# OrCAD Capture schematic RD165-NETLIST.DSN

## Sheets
1 3: size A3
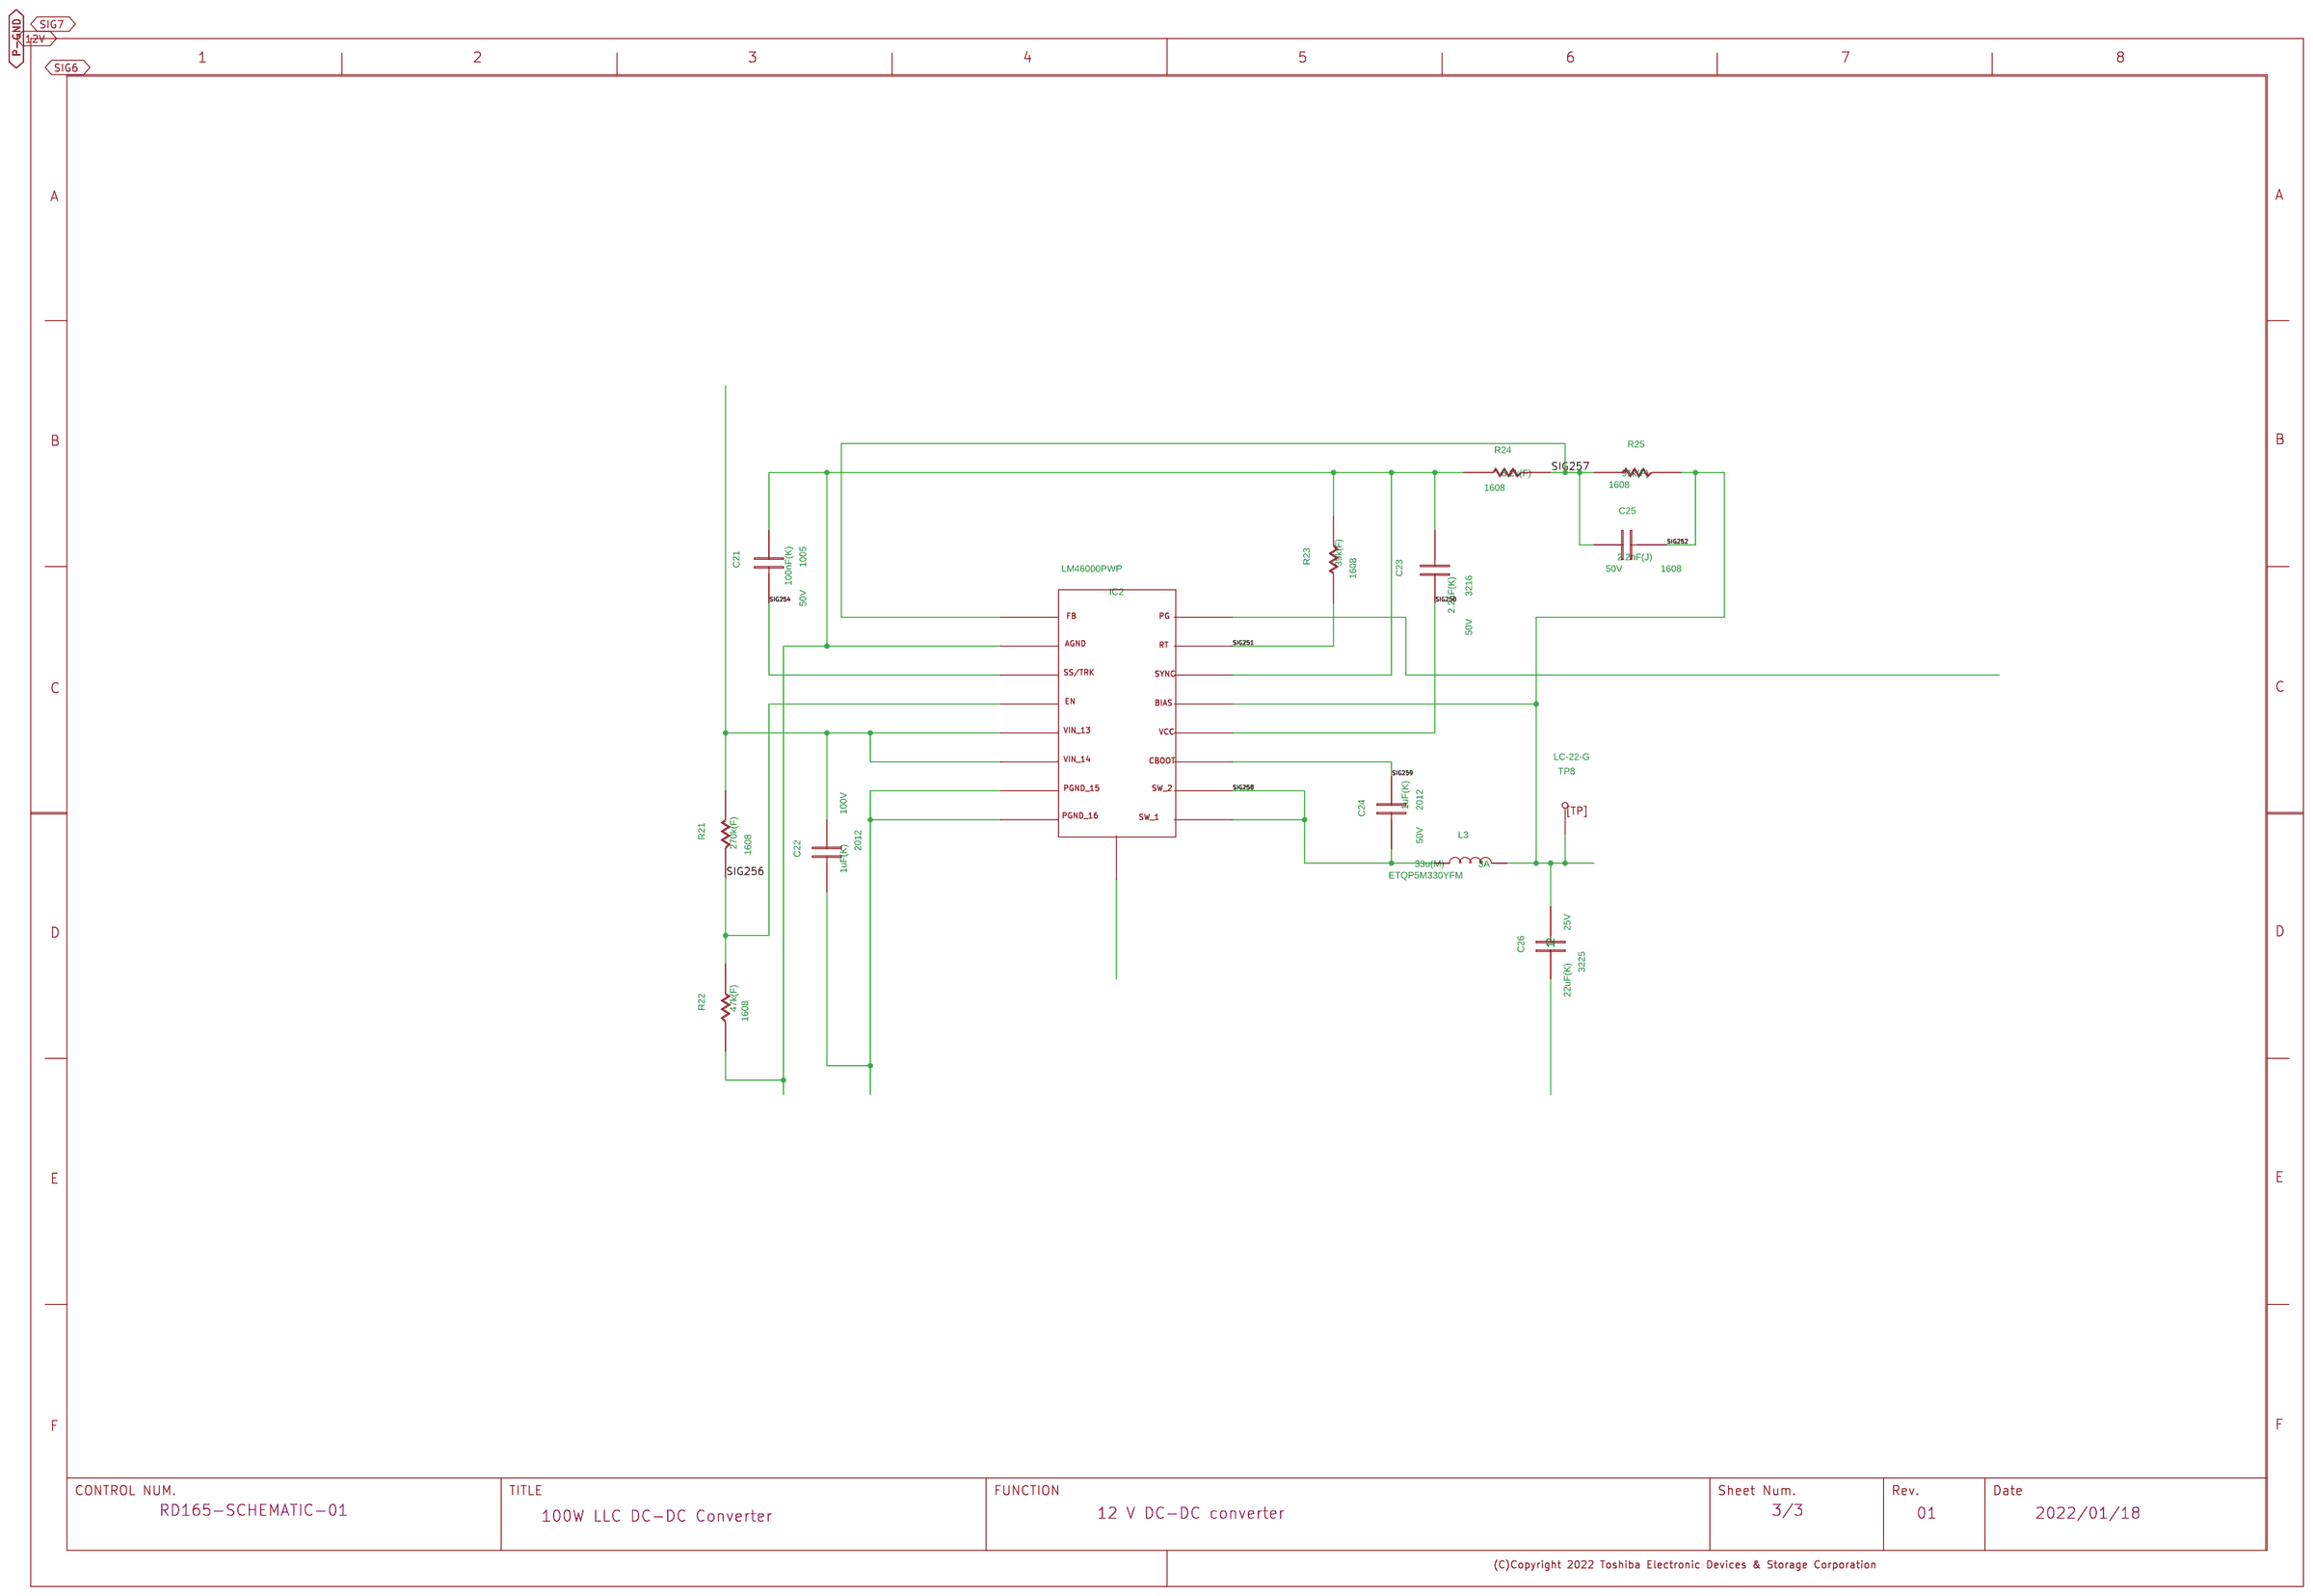
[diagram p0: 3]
2 2: size A3
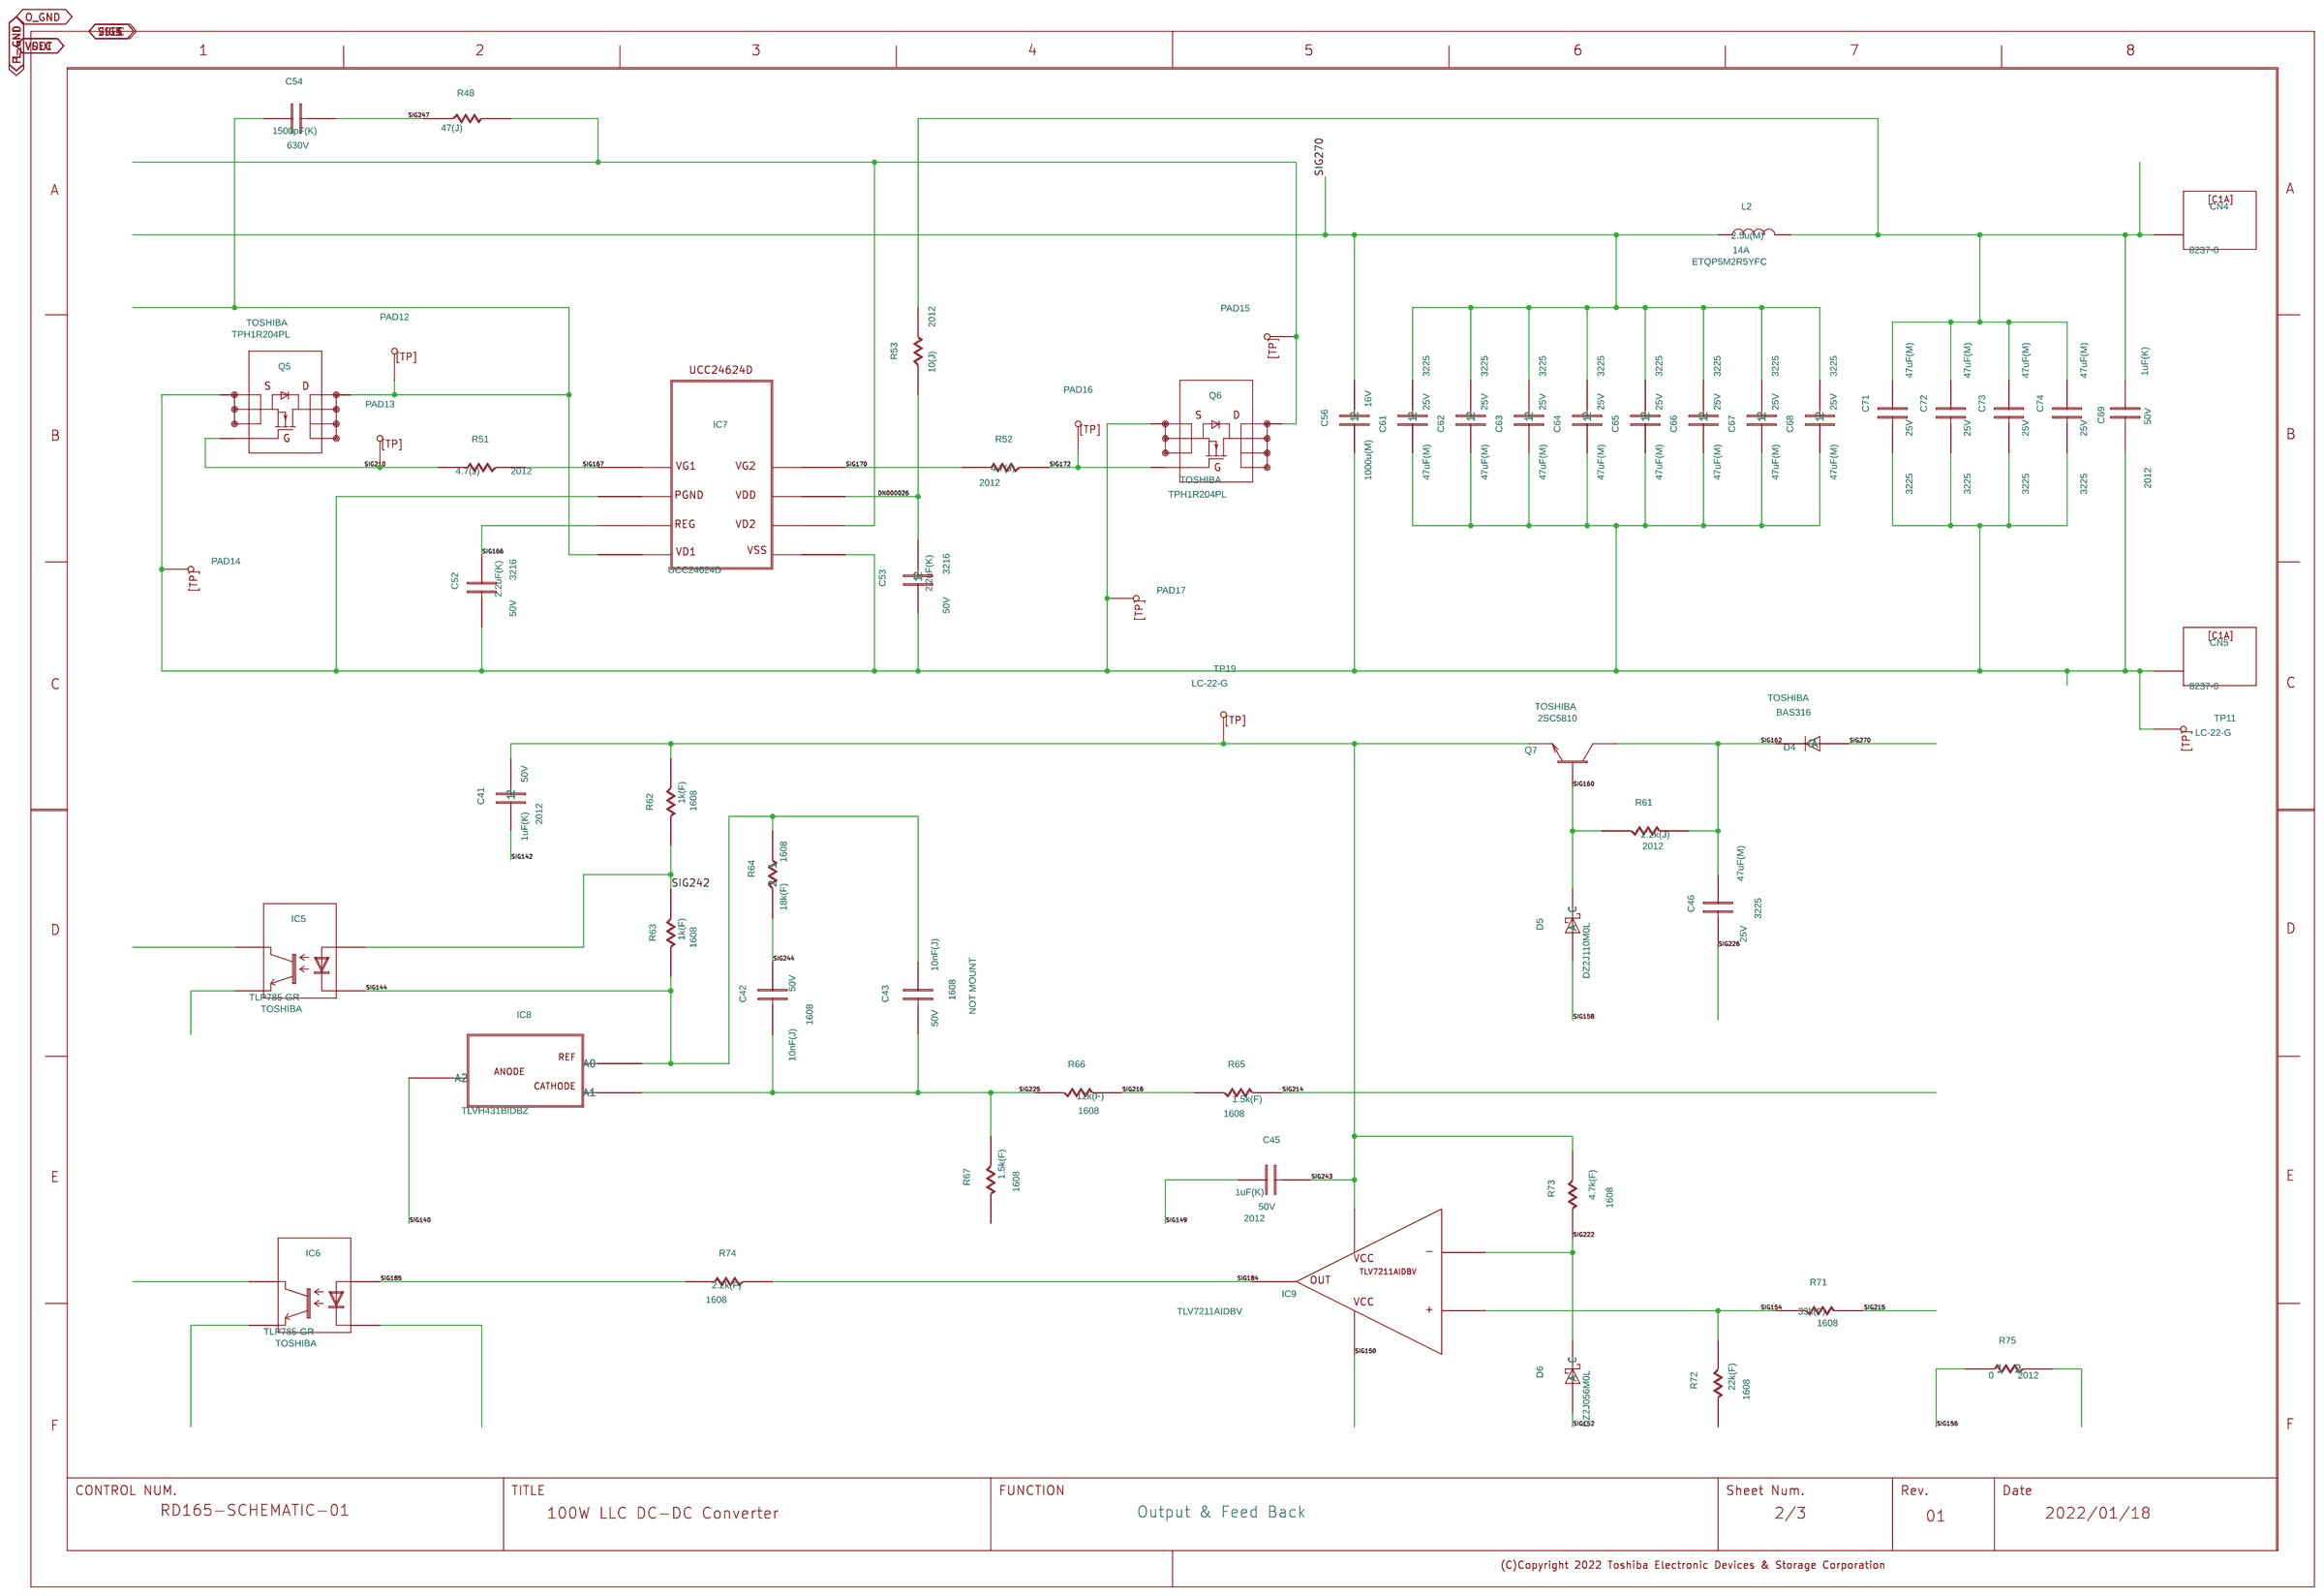
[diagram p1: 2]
3 1: size A3
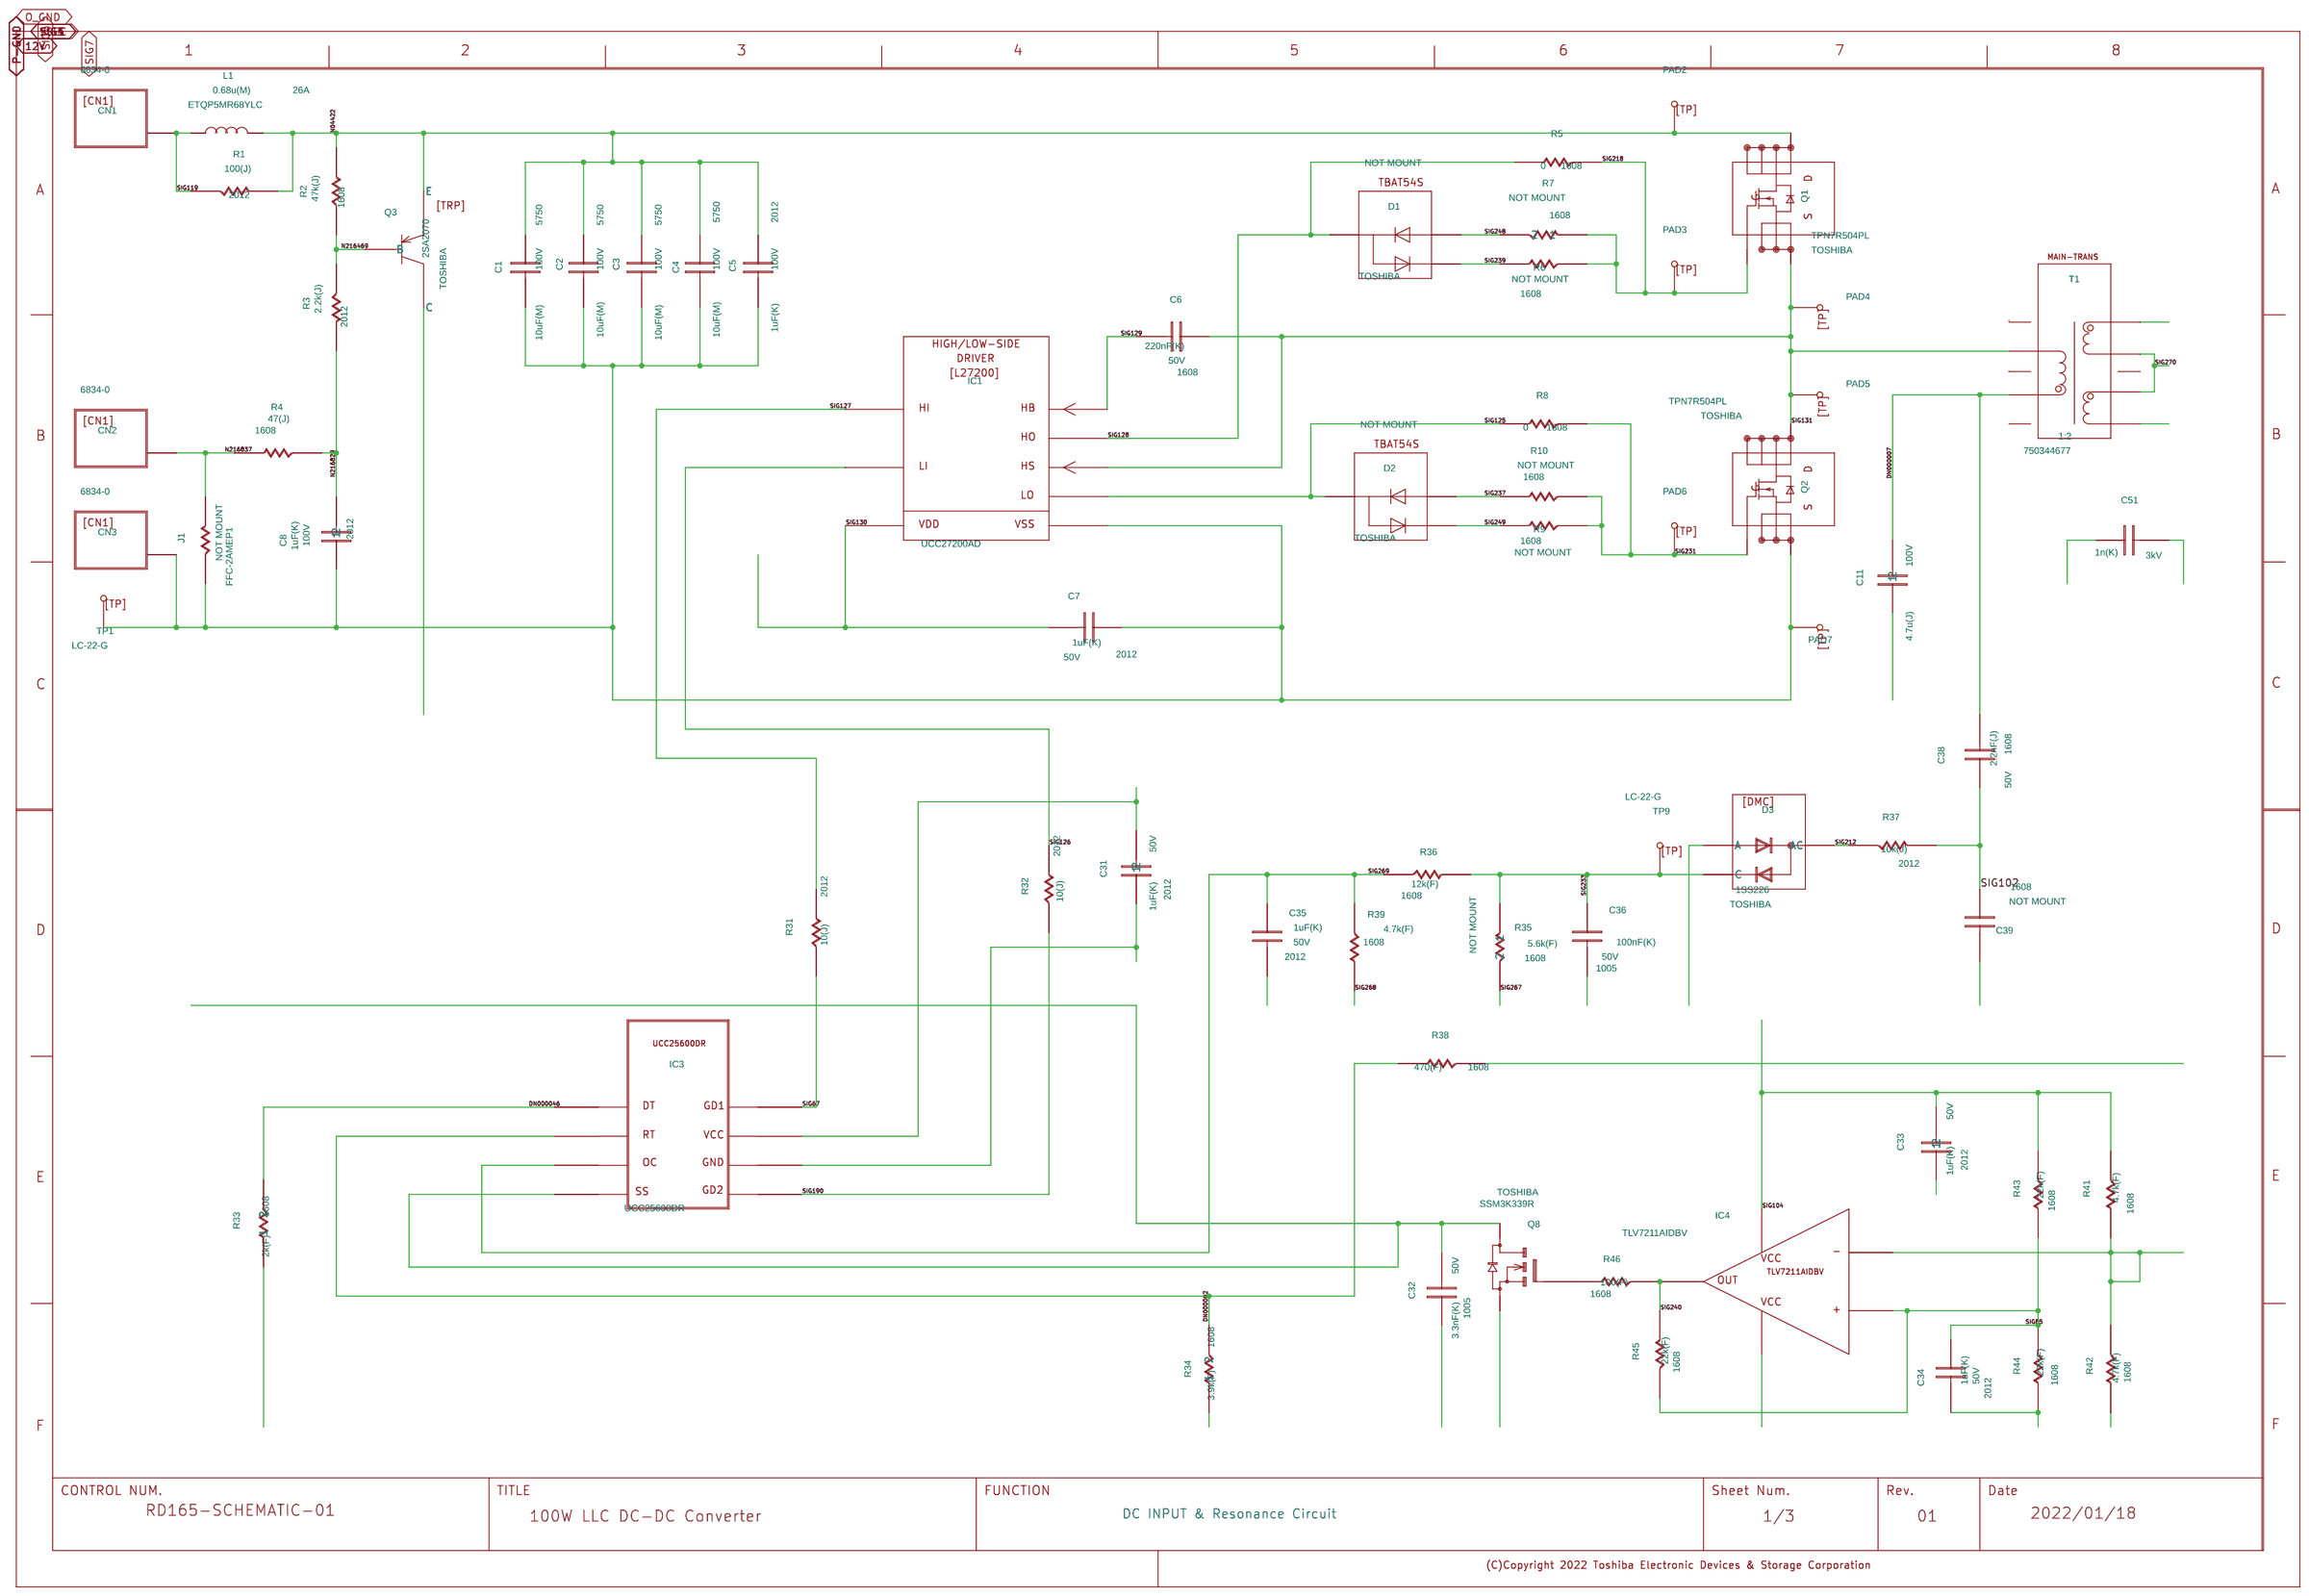
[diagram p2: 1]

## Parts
sheet 1
C1  C
C2  C
C3  C
C4  C
C5  C
C6  C
C7  C
C8  C
C11  C
C31  C
C32  C
C33  C
C34  C
C35  C
C36  C
C38  C
C39  C
C51  C
CN1  CN1
CN2  CN1
CN3  CN1
D1  TBAT54S
D2  TBAT54S
D3  DMC
IC1  L27200
IC3  UCC25600DR
IC4  TLV7211AIDBV
J1  R
L1  L
PAD2  TP
PAD3  TP
PAD4  TP
PAD5  TP
PAD6  TP
PAD7  TP
Q1  TPN7B504PL
Q2  TPN7B504PL
Q3  TRP
Q8  MFNF
R1  R
R2  R
R3  R
R4  R
R5  R
R6  R
R7  R
R8  R
R9  R
R10  R
R31  R
R32  R
R33  R
R34  R
R35  R
R36  R
R37  R
R38  R
R39  R
R41  R
R42  R
R43  R
R44  R
R45  R
R46  R
T1  TRANS
TP1  TP
TP9  TP
U?#2  WAKU_DEF100
sheet 2
C41  C
C42  C
C43  C
C45  C
C46  C
C52  C
C53  C
C54  C
C56  C
C61  C
C62  C
C63  C
C64  C
C65  C
C66  C
C67  C
C68  C
C69  C
C71  C
C72  C
C73  C
C74  C
CN4  C1A
CN5  C1A
D4  D
D5  SBD
D6  SBD
IC5  TLP785-GR
IC6  TLP785-GR
IC7  UCC24624D
IC8  HC086_GATE
IC9  TLV7211AIDBV
L2  L
PAD12  TP
PAD13  TP
PAD14  TP
PAD15  TP
PAD16  TP
PAD17  TP
Q5  TPH1R204PL
Q6  TPH1R204PL
Q7  2SC5810
R48  R
R51  R
R52  R
R53  R
R61  R
R62  R
R63  R
R64  R
R65  R
R66  R
R67  R
R71  R
R72  R
R73  R
R74  R
R75  R
TP11  TP
TP19  TP
U?#1  WAKU_DEF100
sheet 3
C21  C
C22  C
C23  C
C24  C
C25  C
C26  C
IC2  LM46000PWP
L3  L
R21  R
R22  R
R23  R
R24  R
R25  R
TP8  TP
U?#3  WAKU_DEF100

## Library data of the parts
C1-C4 = C: ADSMODELNAME: s_CX55Y5U106M50AT; CAPACITANCETOLE: M; CDBNAME: Chip5750_TD; CDMASTERCADCELG: DC848R; COMP: Chip5750_TD; COMPONENTTYPE: 4; FNLEADFREETHET1GT2GMCTH1: N_N_N; GCOUNT: 1; MAXGCOUNT: 1; NOMINALCAPACITA: 10u; OUMECLASSIFICATION: ƒZƒ‰ƒ~ƒbƒNƒRƒ“ƒfƒ“ƒT; OUMEMAKER: KYC ‹žƒZƒ‰; OUMEMAKERKATAMEI: CX55Y5U106M50AT; QUADMODEL: CON_10U; RATEDVOLTAGE: 50; SIZECODESMD: 5750; TEMPCHARACTERI2: E; VAL1: 10uF(M); VAL2: 100V
C5 = C: ADSMODELNAME: s_CGA4J3X7S2A105KT@@; CAPACITANCETOLE: K; CDBNAME: Chip2012_GS_1; CDMASTERCADCELG: KC0136; COMP: Chip2012_GS_1; COMPONENTTYPE: 4; FNLEADFREETHET1GT2GMCTH1: 3_2_N; GCOUNT: 1; MAXGCOUNT: 1; NOMINALCAPACITA: 1u; OUMECLASSIFICATION: ƒZƒ‰ƒ~ƒbƒNƒRƒ“ƒfƒ“ƒT; OUMEMAKER: TDK ‚s‚c‚j; OUMEMAKERKATAMEI: CGA4J3X7S2A105KT@@; PMPRODUCTSTYPEG: HEV; QUADMODEL: CON_1U; RATEDVOLTAGE: 100; SIZECODESMD: 2012; VAL1: 1uF(K); VAL2: 100V
C6 = C: ADSMODELNAME: s_CGA3E3X7R1H224KT@@; CAPACITANCETOLE: K; CDBNAME: Chip1608_GS_1; CDMASTERCADCELG: KCK0238; COMP: Chip1608_GS_1; COMPONENTTYPE: 4; FNLEADFREETHET1GT2GMCTH1: N_N_N; GCOUNT: 1; MAXGCOUNT: 1; NOMINALCAPACITA: 220n; OUMECLASSIFICATION: ƒZƒ‰ƒ~ƒbƒNƒRƒ“ƒfƒ“ƒT; OUMEMAKER: TDK ‚s‚c‚j; OUMEMAKERKATAMEI: CGA3E3X7R1H224KT@@; PMPRODUCTSTYPEG: DA; QUADMODEL: CON_220N; RATEDVOLTAGE: 50; SIZECODESMD: 1608; VAL1: 220nF(K); VAL2: 50V
C7 C24 C34 C45 C69 = C: ADSMODELNAME: s_CGA4J3X7R1H105KT@@; CAPACITANCETOLE: K; CDBNAME: Chip2012_GS_1; CDMASTERCADCELG: KC0159; COMP: Chip2012_GS_1; COMPONENTTYPE: 4; FNLEADFREETHET1GT2GMCTH1: 3_2_N; GCOUNT: 1; MAXGCOUNT: 1; NOMINALCAPACITA: 1u; OUMECLASSIFICATION: ƒZƒ‰ƒ~ƒbƒNƒRƒ“ƒfƒ“ƒT; OUMEMAKER: TDK ‚s‚c‚j; OUMEMAKERKATAMEI: CGA4J3X7R1H105KT@@; PMPRODUCTSTYPEG: DA; QUADMODEL: CON_1U; RATEDVOLTAGE: 50; SIZECODESMD: 2012; VAL1: 1uF(K); VAL2: 50V
C8 = C#1: ADSMODELNAME: s_CGA4J3X7R1H105KT@@; CAPACITANCETOLE: K; CDBNAME: Chip2012_GS_1; CDMASTERCADCELG: KC0159; COMP: Chip2012_GS_1; COMPONENTTYPE: 4; CaptureCellPackProp: C##1; FNLEADFREETHET1GT2GMCTH1: 3_2_N; GCOUNT: 1; MAXGCOUNT: 1; NOMINALCAPACITA: 1u; OUMECLASSIFICATION: ƒZƒ‰ƒ~ƒbƒNƒRƒ“ƒfƒ“ƒT; OUMEMAKER: TDK ‚s‚c‚j; OUMEMAKERKATAMEI: CGA4J3X7R1H105KT@@; PMPRODUCTSTYPEG: DA; QUADMODEL: CON_1U; RATEDVOLTAGE: 50; SIZECODESMD: 2012; VAL1: 1uF(K); VAL2: 100V
C11 = C#1: CDBNAME: CB182E0475***_AV; COMP: CB182E0475***_AV; COMPONENTTYPE: 4; CaptureCellPackProp: C##1; VAL1: 4.7u(J); VAL2: 100V
C31 C41 = C#1: ADSMODELNAME: s_CGA4J3X7R1H105KT@@; CAPACITANCETOLE: K; CDBNAME: Chip2012_GS_1; CDMASTERCADCELG: KC0159; COMP: Chip2012_GS_1; COMPONENTTYPE: 4; CaptureCellPackProp: C##1; FNLEADFREETHET1GT2GMCTH1: 3_2_N; GCOUNT: 1; MAXGCOUNT: 1; NOMINALCAPACITA: 1u; OUMECLASSIFICATION: ƒZƒ‰ƒ~ƒbƒNƒRƒ“ƒfƒ“ƒT; OUMEMAKER: TDK ‚s‚c‚j; OUMEMAKERKATAMEI: CGA4J3X7R1H105KT@@; PMPRODUCTSTYPEG: DA; QUADMODEL: CON_1U; RATEDVOLTAGE: 50; SIZECODESMD: 2012; VAL1: 1uF(K); VAL2: 50V
C32 = C: ADSMODELNAME: s_CGA2B3X7R1H103KT@@; CAPACITANCETOLE: K; CDBNAME: Chip1005_GS_2; CDMASTERCADCELG: KC0154; COMP: Chip1005_GS_2; COMPONENTTYPE: 4; FNLEADFREETHET1GT2GMCTH1: 3_0_N; GCOUNT: 1; MAXGCOUNT: 1; NOMINALCAPACITA: 10n; OUMECLASSIFICATION: ƒZƒ‰ƒ~ƒbƒNƒRƒ“ƒfƒ“ƒT; OUMEMAKER: TDK ‚s‚c‚j; OUMEMAKERKATAMEI: CGA2B3X7R1H103KT@@; PMPRODUCTSTYPEG: DA; QUADMODEL: CON_10N; RATEDVOLTAGE: 50; SIZECODESMD: 1005; VAL1: 3.3nF(K); VAL2: 50V
C33 = C#1: ADSMODELNAME: s_CGA4J3X7R1H105KTXXXS@@; CAPACITANCETOLE: K; CDBNAME: Chip2012_GS_1; CDMASTERCADCELG: KC0187; COMP: Chip2012_GS_1; COMPONENTTYPE: 4; CaptureCellPackProp: C##1; FNLEADFREETHET1GT2GMCTH1: 3_2_N; GCOUNT: 1; MAXGCOUNT: 1; NOMINALCAPACITA: 1u; OUMECLASSIFICATION: ƒZƒ‰ƒ~ƒbƒNƒRƒ“ƒfƒ“ƒT; OUMEMAKER: TDK ‚s‚c‚j; OUMEMAKERKATAMEI: CGA4J3X7R1H105KTXXXS@@; PMPRODUCTSTYPEG: DA; QUADMODEL: CON_1U; RATEDVOLTAGE: 50; SIZECODESMD: 2012; VAL1: 1uF(K); VAL2: 50V
C35 = C: CDBNAME: Chip2012_GS_1; COMP: Chip2012_GS_1; COMPONENTTYPE: 4; SIZECODESMD: 2012; VAL1: 1uF(K); VAL2: 50V
C36 = C: CDBNAME: Chip1005_GS_2; COMP: Chip1005_GS_2; COMPONENTTYPE: 4; SIZECODESMD: 1005; VAL1: 100nF(K); VAL2: 50V
C38 = C: ADSMODELNAME: s_GCM1885C1H222JA16D@@; CAPACITANCETOLE: J; CDBNAME: Chip1608_GS_1; CDMASTERCADCELG: KC0134; COMP: Chip1608_GS_1; COMPONENTTYPE: 4; FNLEADFREETHET1GT2GMCTH1: 3_2_N; GCOUNT: 1; MAXGCOUNT: 1; NOMINALCAPACITA: 2.2n; OUMECLASSIFICATION: ƒZƒ‰ƒ~ƒbƒNƒRƒ“ƒfƒ“ƒT; OUMEMAKER: MRT ºc»ì; OUMEMAKERKATAMEI: GCM1885C1H222JA16D@@; PMPRODUCTSTYPEG: HEV; QUADMODEL: CON_2.2N; RATEDVOLTAGE: 50; SIZECODESMD: 1608; VAL1: 2.2nF(J); VAL2: 50V
C39 C43 = C: ADSMODELNAME: s_CGA3E2C0G1H103JT@@; CAPACITANCETOLE: J; CDBNAME: Chip1608_GS_1; CDMASTERCADCELG: KC0134; COMP: Chip1608_GS_1; COMPONENTTYPE: 4; FNLEADFREETHET1GT2GMCTH1: 3_2_N; GCOUNT: 1; MAXGCOUNT: 1; NOMINALCAPACITA: 10n; NOTMOUNT: NOT MOUNT; OUMECLASSIFICATION: ƒZƒ‰ƒ~ƒbƒNƒRƒ“ƒfƒ“ƒT; OUMEMAKER: TDK ‚s‚c‚j; OUMEMAKERKATAMEI: CGA3E2C0G1H103JT@@; PMPRODUCTSTYPEG: HEV; QUADMODEL: CON_10N; RATEDVOLTAGE: 50; SIZECODESMD: 1608; VAL1: 10nF(J); VAL2: 50V
C51 = C: CDBNAME: Chip4632_AV; COMP: Chip4632_AV; COMPONENTTYPE: 4; VAL1: 1n(K); VAL2: 3kV
CN1-CN3 = CN1: CDBNAME: 6834-0-00-**-00-00-03-0_ML; CDMASTERCADCELG: CU0059; COMP: 6834-0-00-**-00-00-03-0_ML; COMPONENTTYPE: 4; FNLEADFREETHET1GT2GMCTH1: 9_1_N; GCOUNT: 1; MAXGCOUNT: 1; NUMBEROFCONTACT: 1; OUMECLASSIFICATION: ’P“ªƒvƒ‰ƒO; OUMEMAKER: SMK ƒGƒXƒGƒƒPƒC; OUMEMAKERKATAMEI: CMI1501-0101; OUMEPARTTYPE: CN; PLUGDIAMETER: 6m; RATEDVOLTAGE: 0; VAL1: 6834-0; VAL3: 6834-0
D1 D2 = TBAT54S: CDBNAME: TBAT54S_TS; COMP: TBAT54S_TS; COMPONENTTYPE: 4; NOTMOUNT: NOT MOUNT; USERCOMPTEXT3: TOSHIBA
D3 = DMC: ADSMODELNAME: s_1SS226_TE85R_; CDBNAME: 1SS226_TS; CDMASTERCADCELG: DD902A; COMP: 1SS226_TS; COMPONENTTYPE: 4; FNLEADFREETHET1GT2GMCTH1: 2_0_N; FORWARDVOLTAGEM: 0; GCOUNT: 1; MAXAVERAGEFORWA: 0; MAXGCOUNT: 1; MAXREPETITIVEPE: 0; MAXREVERSEVOLTA: 70; MOUNTINGFORMSMD: SMD; OUMECLASSIFICATION: ¬M_CI[h; OUMEMAKER: TSB “ŒŽÅ; OUMEMAKERKATAMEI: 1SS226(TE85R); OUMEPARTTYPE: D; PEAKFORWARDVOLT: 0; PMPRODUCTSTYPEG: PC1; REVERSECURRENT: 0; USERCOMPTEXT3: TOSHIBA; VAL1: 1SS226; VAL3: 1SS226; ZENERVOLTAGEMAX: 0; ZENERVOLTAGEMIN: 0
IC1 = L27200: CDBNAME: UCC272**AD_TI; CDMASTERCADCELG: I810D8; COMP: UCC272**AD_TI; COMPONENTTYPE: 4; FNLEADFREETHET1GT2GMCTH1: N_N_N; GCOUNT: 1; KIND: OTHER; MAXGCOUNT: 1; MOUNTINGFORMSMD: SMD; OUMECLASSIFICATION: ‚»‚Ì‘¼; OUMEMAKER: TII eLTXCXcc; OUMEMAKERKATAMEI: UCC27200D; OUMEPARTTYPE: IC; VAL1: UCC27200AD; VAL3: UCC27200AD
IC3 = UCC25600DR: CDBNAME: UCC25600D*_TI; COMP: UCC25600D*_TI; COMPONENTTYPE: 4
IC4 IC9 = TLV7211AIDBV: CDBNAME: TLV7211AIDBVR_TI; COMP: TLV7211AIDBVR_TI; COMPONENTTYPE: 4
J1 = R: CDBNAME: FFC-2AMEP1_HN; COMP: FFC-2AMEP1_HN; COMPONENTTYPE: 4; NOTMOUNT: NOT MOUNT; VAL1: FFC-2AMEP1; VAL3: FFC-2AMEP1
L1 = L: CDBNAME: ETQP5M***YLC_PN; COMP: ETQP5M***YLC_PN; COMPONENTTYPE: 4; VAL1: 0.68u(M); VAL2: 26A; VAL3: ETQP5MR68YLC
PAD2-PAD7 PAD12-PAD17 = TP: CDBNAME: TP_I_TH0.5_LC1.1_RC1.2_GS; COMP: TP_I_TH0.5_LC1.1_RC1.2_GS; COMPONENTTYPE: 4
Q1 Q2 = TPN7B504PL: CDBNAME: TPN7R504PL_TS_A; COMP: TPN7R504PL_TS_A; COMPONENTTYPE: 4; SAVEAREA0: -19342,-136,26697,27151; SAVECOUNT: 22; UPDATEDATE: 2019/09/20; UPDATETIME: 14:39:22; USERCOMPTEXT3: TOSHIBA; VAL1: TPN7R504PL; VAL3: TPN7R504PL
Q3 = TRP: ADSMODELNAME: s_2SA2070_TE12L_F_; CDBNAME: 2SA2070_TS; CDMASTERCADCELG: DQ901D; COMP: 2SA2070_TS; COMPONENTTYPE: 4; FNLEADFREETHET1GT2GMCTH1: N_N_N; GCOUNT: 1; MAXCBVOLTAGE: 0; MAXCEVOLTAGE: 0; MAXCOLLECTORCUR: -1; MAXDRAINCURRENT: 0; MAXDSVOLTAGE: 0; MAXEBVOLTAGE: 0; MAXGATECURRENT: 0; MAXGCOUNT: 1; MAXGDVOLTAGE: 0; MAXGSVOLTAGE: 0; MOUNTINGFORMSMD: SMD; OUMECLASSIFICATION: PNPoC|[gWX^; OUMEMAKER: TSB “ŒŽÅ; OUMEMAKERKATAMEI: 2SA2070(TE12L,F); OUMEPARTTYPE: Q; PMPRODUCTSTYPEG: HD1; USERCOMPTEXT3: TOSHIBA; VAL1: 2SA2070; VAL3: 2SA2070
Q8 = MFNF: CDBNAME: SSM3K339R_TS_A; COMP: SSM3K339R_TS_A; COMPONENTTYPE: 4; USERCOMPTEXT3: TOSHIBA; VAL1: SSM3K339R; VAL3: SSM3K339R
R1 = R: ADSMODELNAME: s_ERJP06J101V; CDBNAME: Chip2012_GS_1; CDMASTERCADCELG: KC0006; COMP: Chip2012_GS_1; COMPONENTTYPE: 4; FNLEADFREETHET1GT2GMCTH1: 2_2_N; GCOUNT: 1; MAXGCOUNT: 1; MOUNTINGFORMSMD: SMD; NOMINALRESISTAN: 100; OUMECLASSIFICATION: \ÊÀpÅèïRí; OUMEMAKER: NAE pi\jbNGNgjbNfoCX; OUMEMAKERKATAMEI: ERJP06J101V; PMPRODUCTSTYPEG: PC1-PCS; POWERRATING: 250m; QUADMODEL: RES_100; RESISTANCETOLER: J; SIZECODESMD: 2012; VAL1: 100(J); VAL2: 400mW
R2 = R: ADSMODELNAME: s_ERJ3GEYJ473V@@; CDBNAME: Chip1608_GS_1; CDMASTERCADCELG: KC0133; COMP: Chip1608_GS_1; COMPONENTTYPE: 4; FNLEADFREETHET1GT2GMCTH1: 3_2_N; GCOUNT: 1; MAXGCOUNT: 1; MOUNTINGFORMSMD: SMD; NOMINALRESISTAN: 47K; OUMECLASSIFICATION: \ÊÀpÅèïRí; OUMEMAKER: NAE pi\jbNGNgjbNfoCX; OUMEMAKERKATAMEI: ERJ3GEYJ473V@@; PMPRODUCTSTYPEG: HEV; POWERRATING: 100m; QUADMODEL: RES_47K; RESISTANCETOLER: J; SIZECODESMD: 1608; VAL1: 47k(J); VAL2: 100mW
R3 R61 = R: ADSMODELNAME: s_SG73P2ATTD222J@@; CDBNAME: Chip2012_GS_1; CDMASTERCADCELG: KC0135; COMP: Chip2012_GS_1; COMPONENTTYPE: 4; FNLEADFREETHET1GT2GMCTH1: 3_1_N; GCOUNT: 1; MAXGCOUNT: 1; MOUNTINGFORMSMD: SMD; NOMINALRESISTAN: 2.2K; OUMECLASSIFICATION: \ÊÀpÅèïRí; OUMEMAKER: KOA R[A; OUMEMAKERKATAMEI: SG73P2ATTD222J@@; PMPRODUCTSTYPEG: HEV; POWERRATING: 250m; QUADMODEL: RES_2.2K; RESISTANCETOLER: J; SIZECODESMD: 2012; VAL1: 2.2k(J); VAL2: 400mW
R4 = R: ADSMODELNAME: s_RK73B1JTTD470J@@; CDBNAME: Chip1608_GS_1; CDMASTERCADCELG: KC0133; COMP: Chip1608_GS_1; COMPONENTTYPE: 4; FNLEADFREETHET1GT2GMCTH1: 3_1_N; GCOUNT: 1; MAXGCOUNT: 1; MOUNTINGFORMSMD: SMD; NOMINALRESISTAN: 47; OUMECLASSIFICATION: \ÊÀpÅèïRí; OUMEMAKER: KOA R[A; OUMEMAKERKATAMEI: RK73B1JTTD470J@@; PMPRODUCTSTYPEG: HEV; POWERRATING: 100m; QUADMODEL: RES_47; RESISTANCETOLER: J; SIZECODESMD: 1608; VAL1: 47(J); VAL2: 100mW
R5 R8 = R: ADSMODELNAME: s_CR1_16_000V_HSF; CDBNAME: Chip1608_GS_1; CDMASTERCADCELG: KC0167; COMP: Chip1608_GS_1; COMPONENTTYPE: 4; FNLEADFREETHET1GT2GMCTH1: 2_1_N; GCOUNT: 1; MAXGCOUNT: 1; MOUNTINGFORMSMD: SMD; NOMINALRESISTAN: 0; OUMECLASSIFICATION: \ÊÀpÅèïRí; OUMEMAKER: HDK k¤dCHÆ; OUMEMAKERKATAMEI: CR1/16 000V HSF; PMPRODUCTSTYPEG: HD1; POWERRATING: 100m; QUADMODEL: RES_0; RESISTANCETOLER: X; SIZECODESMD: 1608; VAL1: 0; VAL2: 100mW
R6 R9 R10 = R: ADSMODELNAME: s_ERJ3GEYF100V; CDBNAME: Chip1608_GS_1; CDMASTERCADCELG: DR802R; COMP: Chip1608_GS_1; COMPONENTTYPE: 4; FNLEADFREETHET1GT2GMCTH1: 3_1_N; GCOUNT: 1; MAXGCOUNT: 1; MOUNTINGFORMSMD: SMD; NOMINALRESISTAN: 10; NOTMOUNT: NOT MOUNT; OUMECLASSIFICATION: \ÊÀpÅèïRí; OUMEMAKER: NAE pi\jbNGNgjbNfoCX; OUMEMAKERKATAMEI: ERJ3GEYF100V; POWERRATING: 63m; QUADMODEL: RES_10; RESISTANCETOLER: F; SIZECODESMD: 1608; VAL1: 10(F); VAL2: 100mW
R7 = R#1: ADSMODELNAME: s_ERJ3GEYF100V; CDBNAME: Chip1608_GS_1; CDMASTERCADCELG: DR802R; COMP: Chip1608_GS_1; COMPONENTTYPE: 4; CaptureCellPackProp: R##1; FNLEADFREETHET1GT2GMCTH1: 3_1_N; GCOUNT: 1; MAXGCOUNT: 1; MOUNTINGFORMSMD: SMD; NOMINALRESISTAN: 10; NOTMOUNT: NOT MOUNT; OUMECLASSIFICATION: \ÊÀpÅèïRí; OUMEMAKER: NAE pi\jbNGNgjbNfoCX; OUMEMAKERKATAMEI: ERJ3GEYF100V; POWERRATING: 63m; QUADMODEL: RES_10; RESISTANCETOLER: F; SIZECODESMD: 1608; VAL1: 10(F); VAL2: 100mW
R31 R32 R53 = R: ADSMODELNAME: s__SV_ERJ6GEYJ100V; CDBNAME: Chip2012_GS_1; CDMASTERCADCELG: KCK0273; COMP: Chip2012_GS_1; COMPONENTTYPE: 4; FNLEADFREETHET1GT2GMCTH1: N_N_N; GCOUNT: 1; MAXGCOUNT: 1; MOUNTINGFORMSMD: SMD; NOMINALRESISTAN: 10; OUMECLASSIFICATION: \ÊÀpÅèïRí; OUMEMAKER: NAE pi\jbNGNgjbNfoCX; OUMEMAKERKATAMEI: (SV)ERJ6GEYJ100V; PMPRODUCTSTYPEG: SV1; POWERRATING: 125m; QUADMODEL: RES_10; RESISTANCETOLER: J; SIZECODESMD: 2012; VAL1: 10(J); VAL2: 400mW
R33 = R#1: ADSMODELNAME: s_RK73H1JTTD2001F@@; CDBNAME: Chip1608_GS_1; CDMASTERCADCELG: KC0133; COMP: Chip1608_GS_1; COMPONENTTYPE: 4; CaptureCellPackProp: R##1; FNLEADFREETHET1GT2GMCTH1: 3_1_N; GCOUNT: 1; MAXGCOUNT: 1; MOUNTINGFORMSMD: SMD; NOMINALRESISTAN: 2K; OUMECLASSIFICATION: \ÊÀpÅèïRí; OUMEMAKER: KOA R[A; OUMEMAKERKATAMEI: RK73H1JTTD2001F@@; PMPRODUCTSTYPEG: HEV; POWERRATING: 100m; QUADMODEL: RES_2K; RESISTANCETOLER: F; SIZECODESMD: 1608; VAL1: 2k(F); VAL2: 100mW
R34 = R#1: ADSMODELNAME: s_MCR03EZPFX3901; CDBNAME: Chip1608_GS_1; CDMASTERCADCELG: DR802R; COMP: Chip1608_GS_1; COMPONENTTYPE: 4; CaptureCellPackProp: R##1; FNLEADFREETHET1GT2GMCTH1: 3_1_N; GCOUNT: 1; MAXGCOUNT: 1; MOUNTINGFORMSMD: SMD; NOMINALRESISTAN: 3.9K; OUMECLASSIFICATION: \ÊÀpÅèïRí; OUMEMAKER: ROH [; OUMEMAKERKATAMEI: MCR03EZPFX3901; POWERRATING: 63m; QUADMODEL: RES_3.9K; RESISTANCETOLER: F; SIZECODESMD: 1608; VAL1: 3.9k(F); VAL2: 100mw
R35 = R#1: ADSMODELNAME: s_CR1_16_752FV; CDBNAME: Chip1608_GS_1; CDMASTERCADCELG: DR802R; COMP: Chip1608_GS_1; COMPONENTTYPE: 4; CaptureCellPackProp: R##1; FNLEADFREETHET1GT2GMCTH1: 3_1_N; GCOUNT: 1; MAXGCOUNT: 1; MOUNTINGFORMSMD: SMD; NOMINALRESISTAN: 7.5K; NOTMOUNT: NOT MOUNT; OUMECLASSIFICATION: \ÊÀpÅèïRí; OUMEMAKER: HDK k¤dCHÆ; OUMEMAKERKATAMEI: CR1/16 752FV; POWERRATING: 63m; QUADMODEL: RES_7.5K; RESISTANCETOLER: F; SIZECODESMD: 1608; VAL1: 5.6k(F); VAL2: 100mw
R36 = R: CDBNAME: Chip1608_GS_1; COMP: Chip1608_GS_1; COMPONENTTYPE: 4; SIZECODESMD: 1608; VAL1: 12k(F)
R37 = R: ADSMODELNAME: s_SG73S2ATTD103J; CDBNAME: Chip2012_GS_1; CDMASTERCADCELG: KC0006; COMP: Chip2012_GS_1; COMPONENTTYPE: 4; FNLEADFREETHET1GT2GMCTH1: N_N_N; GCOUNT: 1; MAXGCOUNT: 1; MOUNTINGFORMSMD: SMD; NOMINALRESISTAN: 10K; OUMECLASSIFICATION: \ÊÀpÅèïRí; OUMEMAKER: KOA R[A; OUMEMAKERKATAMEI: SG73S2ATTD103J; PMPRODUCTSTYPEG: DME; POWERRATING: 250m; QUADMODEL: RES_10K; RESISTANCETOLER: J; SIZECODESMD: 2012; VAL1: 10k(J); VAL2: 400mW
R38 = R: ADSMODELNAME: s_RK73H1JRTTD4700F; CDBNAME: Chip1608_GS_1; CDMASTERCADCELG: KC0008; COMP: Chip1608_GS_1; COMPONENTTYPE: 4; FNLEADFREETHET1GT2GMCTH1: N_N_N; GCOUNT: 1; MAXGCOUNT: 1; MOUNTINGFORMSMD: SMD; NOMINALRESISTAN: 470; OUMECLASSIFICATION: \ÊÀpÅèïRí; OUMEMAKER: KOA R[A; OUMEMAKERKATAMEI: RK73H1JRTTD4700F; PMPRODUCTSTYPEG: DME; POWERRATING: 100m; QUADMODEL: RES_470; RESISTANCETOLER: F; SIZECODESMD: 1608; VAL1: 470(F); VAL2: 100mW
R39 = R: CDBNAME: Chip1608_GS_1; COMP: Chip1608_GS_1; COMPONENTTYPE: 4; SIZECODESMD: 1608; VAL1: 4.7k(F)
R41 R42 R73 = R: ADSMODELNAME: s_ERJ3EKF4701V@@; CDBNAME: Chip1608_GS_1; CDMASTERCADCELG: KCK0234; COMP: Chip1608_GS_1; COMPONENTTYPE: 4; FNLEADFREETHET1GT2GMCTH1: N_N_N; GCOUNT: 1; MAXGCOUNT: 1; MOUNTINGFORMSMD: SMD; NOMINALRESISTAN: 4.7K; OUMECLASSIFICATION: \ÊÀpÅèïRí; OUMEMAKER: NAE pi\jbNGNgjbNfoCX; OUMEMAKERKATAMEI: ERJ3EKF4701V@@; PMPRODUCTSTYPEG: DA; POWERRATING: 100m; QUADMODEL: RES_4.7K; RESISTANCETOLER: F; SIZECODESMD: 1608; VAL1: 4.7k(F); VAL2: 100mW
R43-R45 R72 = R: ADSMODELNAME: s_ERJ3EKF2202V; CDBNAME: Chip1608_GS_1; CDMASTERCADCELG: KC0008; COMP: Chip1608_GS_1; COMPONENTTYPE: 4; FNLEADFREETHET1GT2GMCTH1: N_N_N; GCOUNT: 1; MAXGCOUNT: 1; MOUNTINGFORMSMD: SMD; NOMINALRESISTAN: 22K; OUMECLASSIFICATION: \ÊÀpÅèïRí; OUMEMAKER: NAE pi\jbNGNgjbNfoCX; OUMEMAKERKATAMEI: ERJ3EKF2202V; POWERRATING: 100m; QUADMODEL: RES_22K; RESISTANCETOLER: F; SIZECODESMD: 1608; VAL1: 22k(F); VAL2: 100mW
R46 = R: ADSMODELNAME: s_RK73H1JTD1000F; CDBNAME: Chip1608_GS_1; CDMASTERCADCELG: DR802R; COMP: Chip1608_GS_1; COMPONENTTYPE: 4; FNLEADFREETHET1GT2GMCTH1: 3_1_N; GCOUNT: 1; MAXGCOUNT: 1; MOUNTINGFORMSMD: SMD; NOMINALRESISTAN: 100; OUMECLASSIFICATION: \ÊÀpÅèïRí; OUMEMAKER: KOA R[A; OUMEMAKERKATAMEI: RK73H1JTD1000F; POWERRATING: 63m; QUADMODEL: RES_100; RESISTANCETOLER: F; SIZECODESMD: 1608; VAL1: 100(F); VAL2: 100mW
T1 = TRANS: CDBNAME: PC40EER28_GS; COMP: PC40EER28_GS; COMPONENTTYPE: 4; SAVEAREA0: -21734,-9489,47855,41529; SAVECOUNT: 10; UPDATEDATE: 2019/09/24; UPDATETIME: 08:41:46; VAL1: 1:2; VAL3: 750344677
TP1 TP8 TP9 TP11 TP19 = TP: CDBNAME: LC-22_GS; COMP: LC-22_GS; COMPONENTTYPE: 4; VAL1: LC-22-G; VAL3: LC-22-G
U?#2 = WAKU_DEF100: COMPONENTTYPE: 2; DATE: 2022/01/18; DRAWINGNUMBER: RD165-SCHEMATIC-01; REVISION: 01; SAVEAREA0: 198008,-65938,436964,90161; SAVECOUNT: 4; SHEETNUMBER: 1/3; TITLE: 100W LLC DC-DC Converter; UPDATEDATE: 2022/01/19; UPDATETIME: 11:00:47
C42 = C: ADSMODELNAME: s_CGA3E2C0G1H103JT@@; CAPACITANCETOLE: J; CDBNAME: Chip1608_GS_1; CDMASTERCADCELG: KC0134; COMP: Chip1608_GS_1; COMPONENTTYPE: 4; FNLEADFREETHET1GT2GMCTH1: 3_2_N; GCOUNT: 1; MAXGCOUNT: 1; NOMINALCAPACITA: 10n; OUMECLASSIFICATION: ƒZƒ‰ƒ~ƒbƒNƒRƒ“ƒfƒ“ƒT; OUMEMAKER: TDK ‚s‚c‚j; OUMEMAKERKATAMEI: CGA3E2C0G1H103JT@@; PMPRODUCTSTYPEG: HEV; QUADMODEL: CON_10N; RATEDVOLTAGE: 50; SIZECODESMD: 1608; VAL1: 10nF(J); VAL2: 50V
C46 = C: ADSMODELNAME: s_GCM32ER70J476ME19L@@; CAPACITANCETOLE: M; CDBNAME: Chip3225_GS; CDMASTERCADCELG: KC0138; COMP: Chip3225_GS; COMPONENTTYPE: 4; FNLEADFREETHET1GT2GMCTH1: 3_0_N; GCOUNT: 1; MAXGCOUNT: 1; NOMINALCAPACITA: 47u; OUMECLASSIFICATION: ƒZƒ‰ƒ~ƒbƒNƒRƒ“ƒfƒ“ƒT; OUMEMAKER: MRT ºc»ì; OUMEMAKERKATAMEI: GCM32ER70J476ME19L@@; PMPRODUCTSTYPEG: HEV; QUADMODEL: CON_47U; RATEDVOLTAGE: 6.3; SIZECODESMD: 3225; VAL1: 47uF(M); VAL2: 25V
C23 C52 = C: ADSMODELNAME: s_GCM31CR71H225KA55L@@; CAPACITANCETOLE: K; CDBNAME: Chip3216_GS_1; CDMASTERCADCELG: KC0137; COMP: Chip3216_GS_1; COMPONENTTYPE: 4; FNLEADFREETHET1GT2GMCTH1: 3_2_N; GCOUNT: 1; MAXGCOUNT: 1; NOMINALCAPACITA: 2.2u; OUMECLASSIFICATION: ƒZƒ‰ƒ~ƒbƒNƒRƒ“ƒfƒ“ƒT; OUMEMAKER: MRT ºc»ì; OUMEMAKERKATAMEI: GCM31CR71H225KA55L@@; PMPRODUCTSTYPEG: HEV; QUADMODEL: CON_2.2U; RATEDVOLTAGE: 50; SIZECODESMD: 3216; VAL1: 2.2uF(K); VAL2: 50V
C53 = C#1: ADSMODELNAME: s_GCM31CR71H225KA55L@@; CAPACITANCETOLE: K; CDBNAME: Chip3216_GS_1; CDMASTERCADCELG: KC0137; COMP: Chip3216_GS_1; COMPONENTTYPE: 4; CaptureCellPackProp: C##1; FNLEADFREETHET1GT2GMCTH1: 3_2_N; GCOUNT: 1; MAXGCOUNT: 1; NOMINALCAPACITA: 2.2u; OUMECLASSIFICATION: ƒZƒ‰ƒ~ƒbƒNƒRƒ“ƒfƒ“ƒT; OUMEMAKER: MRT ºc»ì; OUMEMAKERKATAMEI: GCM31CR71H225KA55L@@; PMPRODUCTSTYPEG: HEV; QUADMODEL: CON_2.2U; RATEDVOLTAGE: 50; SIZECODESMD: 3216; VAL1: 2.2uF(K); VAL2: 50V
C54 = C: CDBNAME: ECQE2**3*F_PN; COMP: ECQE2**3*F_PN; COMPONENTTYPE: 4; VAL1: 1500pF(K); VAL2: 630V
C56 = C#1: CDBNAME: PCR1****MCL1GS_NC; COMP: PCR1****MCL1GS_NC; COMPONENTTYPE: 4; CaptureCellPackProp: C##1; VAL1: 1000u(M); VAL2: 16V
C61-C68 = C#1: ADSMODELNAME: s_JMK325BJ476MM_T; CAPACITANCETOLE: M; CDBNAME: Chip3225_GS; CDMASTERCADCELG: DC903A; COMP: Chip3225_GS; COMPONENTTYPE: 4; CaptureCellPackProp: C##1; FNLEADFREETHET1GT2GMCTH1: 3_0_N; GCOUNT: 1; MAXGCOUNT: 1; NOMINALCAPACITA: 47u; OUMECLASSIFICATION: ƒZƒ‰ƒ~ƒbƒNƒRƒ“ƒfƒ“ƒT; OUMEMAKER: TYD ‘¾—z—U“d; OUMEMAKERKATAMEI: JMK325BJ476MM-T; PMPRODUCTSTYPEG: SV1; QUADMODEL: CON_47U; RATEDVOLTAGE: 6.3; SIZECODESMD: 3225; TEMPCHARACTERI2: B; VAL1: 47uF(M); VAL2: 25V
C71-C74 = C: ADSMODELNAME: s_JMK325BJ476MM_T; CAPACITANCETOLE: M; CDBNAME: Chip3225_GS; CDMASTERCADCELG: DC903A; COMP: Chip3225_GS; COMPONENTTYPE: 4; FNLEADFREETHET1GT2GMCTH1: 3_0_N; GCOUNT: 1; MAXGCOUNT: 1; NOMINALCAPACITA: 47u; OUMECLASSIFICATION: ƒZƒ‰ƒ~ƒbƒNƒRƒ“ƒfƒ“ƒT; OUMEMAKER: TYD ‘¾—z—U“d; OUMEMAKERKATAMEI: JMK325BJ476MM-T; PMPRODUCTSTYPEG: SV1; QUADMODEL: CON_47U; RATEDVOLTAGE: 6.3; SIZECODESMD: 3225; TEMPCHARACTERI2: B; VAL1: 47uF(M); VAL2: 25V
CN4 CN5 = C1A: CDBNAME: 8237-0-05-**-00-00-03-0_ML; CDMASTERCADCELG: CUK0165; COMP: 8237-0-05-**-00-00-03-0_ML; COMPONENTTYPE: 4; CONTACTPITCH: 0; FNLEADFREETHET1GT2GMCTH1: N_N_N; GCOUNT: 1; MAXGCOUNT: 1; NUMBEROFCONTACT: 1; OUMECLASSIFICATION: ƒvƒŠƒ“ƒg”Â—pŠpŒ`ƒRƒlƒNƒ^; OUMEMAKER: AMP ^CRGNgjNXAv; OUMEMAKERKATAMEI: 87220-1; OUMEPARTTYPE: CN; RATEDCURRENT: 0; VAL1: 8237-0; VAL3: 8237-0
D4 = D: CDBNAME: BAS316_TS_A; COMP: BAS316_TS_A; COMPONENTTYPE: 4; USERCOMPTEXT3: TOSHIBA; VAL1: BAS316; VAL3: BAS316
D5 = SBD: CDBNAME: DZ2J110M0L_PN_A; COMP: DZ2J110M0L_PN_A; COMPONENTTYPE: 4; VAL1: DZ2J110M0L; VAL3: DZ2J110M0L
D6 = SBD: CDBNAME: DZ2J056*0L_PN_A; COMP: DZ2J056*0L_PN_A; COMPONENTTYPE: 4; VAL1: DZ2J056M0L; VAL3: DZ2J056M0L
IC5 IC6 = TLP785-GR: CDBNAME: TLP785_TS_1; COMP: TLP785_TS_1; COMPONENTTYPE: 4; USERCOMPTEXT3: TOSHIBA
IC7 = UCC24624D: CDBNAME: UCC24624D*_TI; COMP: UCC24624D*_TI; COMPONENTTYPE: 4
IC8 = HC086_GATE: CDBNAME: TLVH43***DBZ*_TI; CDMASTERCADCELG: DI830B; COMP: TLVH43***DBZ*_TI; COMPONENTTYPE: 4; FNLEADFREETHET1GT2GMCTH1: N_N_N; GCOUNT: 1; MAXGCOUNT: 4; MOUNTINGFORMSMD: SMD; OUMECLASSIFICATION: CMOSWbN; OUMEMAKER: TSB “ŒŽÅ; OUMEMAKERKATAMEI: TC74HC86F; OUMEPARTTYPE: IC; PROCESS: 74HC; VAL1: TLVH431BIDBZ; VAL3: TLVH431BIDBZ
L2 = L: CDBNAME: ETQP5M***YFC_PN; COMP: ETQP5M***YFC_PN; COMPONENTTYPE: 4; VAL1: 2.5u(M); VAL2: 14A; VAL3: ETQP5M2R5YFC
Q5 Q6 = TPH1R204PL: CDBNAME: TPH1R204PL_TS_A; COMP: TPH1R204PL_TS_A; COMPONENTTYPE: 4; SAVEAREA0: -12325,8914,25768,24851; SAVECOUNT: 19; UPDATEDATE: 2019/09/20; UPDATETIME: 15:06:39; USERCOMPTEXT3: TOSHIBA
Q7 = 2SC5810: CDBNAME: 2SC5810_TS; COMP: 2SC5810_TS; COMPONENTTYPE: 4; USERCOMPTEXT3: TOSHIBA
R48 = R: CDBNAME: MOS1C****_GS_1; COMP: MOS1C****_GS_1; COMPONENTTYPE: 4; VAL1: 47(J); VAL2: 1W
R51 R52 = R: ADSMODELNAME: s_CR1_10_4R7JV; CDBNAME: Chip2012_GS_1; CDMASTERCADCELG: DR910A; COMP: Chip2012_GS_1; COMPONENTTYPE: 4; FNLEADFREETHET1GT2GMCTH1: N_N_N; GCOUNT: 1; MAXGCOUNT: 1; MOUNTINGFORMSMD: SMD; NOMINALRESISTAN: 4.7; OUMECLASSIFICATION: \ÊÀpÅèïRí; OUMEMAKER: HDK k¤dCHÆ; OUMEMAKERKATAMEI: CR1/10 4R7JV; POWERRATING: 100m; QUADMODEL: RES_4.7; RESISTANCETOLER: J; SIZECODESMD: 2012; VAL1: 4.7(J); VAL2: 400mW
R62 R63 = R: ADSMODELNAME: s_RK73H1JRTTD1001F; CDBNAME: Chip1608_GS_1; CDMASTERCADCELG: KC0008; COMP: Chip1608_GS_1; COMPONENTTYPE: 4; FNLEADFREETHET1GT2GMCTH1: N_N_N; GCOUNT: 1; MAXGCOUNT: 1; MOUNTINGFORMSMD: SMD; NOMINALRESISTAN: 1K; OUMECLASSIFICATION: \ÊÀpÅèïRí; OUMEMAKER: KOA R[A; OUMEMAKERKATAMEI: RK73H1JRTTD1001F; PMPRODUCTSTYPEG: DME; POWERRATING: 100m; QUADMODEL: RES_1K; RESISTANCETOLER: F; SIZECODESMD: 1608; VAL1: 1k(F); VAL2: 100mW
R64 = R#1: ADSMODELNAME: s_MCR03EZPFX1802; CDBNAME: Chip1608_GS_1; CDMASTERCADCELG: DR802R; COMP: Chip1608_GS_1; COMPONENTTYPE: 4; CaptureCellPackProp: R##1; FNLEADFREETHET1GT2GMCTH1: 3_1_N; GCOUNT: 1; MAXGCOUNT: 1; MOUNTINGFORMSMD: SMD; NOMINALRESISTAN: 18K; OUMECLASSIFICATION: \ÊÀpÅèïRí; OUMEMAKER: ROH [; OUMEMAKERKATAMEI: MCR03EZPFX1802; POWERRATING: 63m; QUADMODEL: RES_18K; RESISTANCETOLER: F; SIZECODESMD: 1608; VAL1: 18k(F); VAL2: 100mW
R65 R67 = R: ADSMODELNAME: s_CR1_16_152FV; CDBNAME: Chip1608_GS_1; CDMASTERCADCELG: DR802R; COMP: Chip1608_GS_1; COMPONENTTYPE: 4; FNLEADFREETHET1GT2GMCTH1: 3_1_N; GCOUNT: 1; MAXGCOUNT: 1; MOUNTINGFORMSMD: SMD; NOMINALRESISTAN: 1.5K; OUMECLASSIFICATION: \ÊÀpÅèïRí; OUMEMAKER: HDK k¤dCHÆ; OUMEMAKERKATAMEI: CR1/16 152FV; POWERRATING: 63m; QUADMODEL: RES_1.5K; RESISTANCETOLER: F; SIZECODESMD: 1608; VAL1: 1.5k(F); VAL2: 100mW
R66 = R: ADSMODELNAME: s_CR1_16_123FV; CDBNAME: Chip1608_GS_1; CDMASTERCADCELG: DR802R; COMP: Chip1608_GS_1; COMPONENTTYPE: 4; FNLEADFREETHET1GT2GMCTH1: 3_1_N; GCOUNT: 1; MAXGCOUNT: 1; MOUNTINGFORMSMD: SMD; NOMINALRESISTAN: 12K; OUMECLASSIFICATION: \ÊÀpÅèïRí; OUMEMAKER: HDK k¤dCHÆ; OUMEMAKERKATAMEI: CR1/16 123FV; POWERRATING: 63m; QUADMODEL: RES_12K; RESISTANCETOLER: F; SIZECODESMD: 1608; VAL1: 12k(F); VAL2: 100mW
R71 = R: ADSMODELNAME: s_MCR03EZPFX3302; CDBNAME: Chip1608_GS_1; CDMASTERCADCELG: DR802R; COMP: Chip1608_GS_1; COMPONENTTYPE: 4; FNLEADFREETHET1GT2GMCTH1: 3_1_N; GCOUNT: 1; MAXGCOUNT: 1; MOUNTINGFORMSMD: SMD; NOMINALRESISTAN: 33K; OUMECLASSIFICATION: \ÊÀpÅèïRí; OUMEMAKER: ROH [; OUMEMAKERKATAMEI: MCR03EZPFX3302; POWERRATING: 63m; QUADMODEL: RES_33K; RESISTANCETOLER: F; SIZECODESMD: 1608; VAL1: 33k(F); VAL2: 100mW
R74 = R: ADSMODELNAME: s_RK73H1JTTD2201F@@; CDBNAME: Chip1608_GS_1; CDMASTERCADCELG: KC0133; COMP: Chip1608_GS_1; COMPONENTTYPE: 4; FNLEADFREETHET1GT2GMCTH1: 3_1_N; GCOUNT: 1; MAXGCOUNT: 1; MOUNTINGFORMSMD: SMD; NOMINALRESISTAN: 2.2K; OUMECLASSIFICATION: \ÊÀpÅèïRí; OUMEMAKER: KOA R[A; OUMEMAKERKATAMEI: RK73H1JTTD2201F@@; PMPRODUCTSTYPEG: HEV; POWERRATING: 100m; QUADMODEL: RES_2.2K; RESISTANCETOLER: F; SIZECODESMD: 1608; VAL1: 2.2k(F); VAL2: 100mW
R75 = R#1: ADSMODELNAME: s_RK73Z2ATTD; CDBNAME: Chip2012_GS_1; CDMASTERCADCELG: KCK0211; COMP: Chip2012_GS_1; COMPONENTTYPE: 4; CaptureCellPackProp: R##1; FNLEADFREETHET1GT2GMCTH1: 3_2_N; GCOUNT: 1; MAXGCOUNT: 1; MOUNTINGFORMSMD: SMD; NOMINALRESISTAN: 0; OUMECLASSIFICATION: \ÊÀpÅèïRí; OUMEMAKER: KOA R[A; OUMEMAKERKATAMEI: RK73Z2ATTD; PMPRODUCTSTYPEG: DME-PC1; POWERRATING: 125m; QUADMODEL: RES_0; RESISTANCETOLER: X; SIZECODESMD: 2012; VAL1: 0; VAL2: 400mW
U?#1 = WAKU_DEF100: COMPONENTTYPE: 2; DATE: 2022/01/18; DRAWINGNUMBER: RD165-SCHEMATIC-01; REVISION: 01; SAVEAREA0: 198008,-65938,436964,90161; SAVECOUNT: 4; SHEETNUMBER: 2/3; TITLE: 100W LLC DC-DC Converter; UPDATEDATE: 2022/01/19; UPDATETIME: 11:02:38
C21 = C: ADSMODELNAME: s_C1005JB0J104KT; CAPACITANCETOLE: K; CDBNAME: Chip1005_GS_2; CDMASTERCADCELG: DC834K; COMP: Chip1005_GS_2; COMPONENTTYPE: 4; FNLEADFREETHET1GT2GMCTH1: N_N_N; GCOUNT: 1; MAXGCOUNT: 1; NOMINALCAPACITA: 100n; OUMECLASSIFICATION: ƒZƒ‰ƒ~ƒbƒNƒRƒ“ƒfƒ“ƒT; OUMEMAKER: TDK ‚s‚c‚j; OUMEMAKERKATAMEI: C1005JB0J104KT; QUADMODEL: CON_100N; RATEDVOLTAGE: 50; SIZECODESMD: 1005; TEMPCHARACTERI2: B; VAL1: 100nF(K); VAL2: 50V
C22 = C: ADSMODELNAME: s_CGA4J3X7R1H105KT@@; CAPACITANCETOLE: K; CDBNAME: Chip2012_GS_1; CDMASTERCADCELG: KC0159; COMP: Chip2012_GS_1; COMPONENTTYPE: 4; FNLEADFREETHET1GT2GMCTH1: 3_2_N; GCOUNT: 1; MAXGCOUNT: 1; NOMINALCAPACITA: 1u; OUMECLASSIFICATION: ƒZƒ‰ƒ~ƒbƒNƒRƒ“ƒfƒ“ƒT; OUMEMAKER: TDK ‚s‚c‚j; OUMEMAKERKATAMEI: CGA4J3X7R1H105KT@@; PMPRODUCTSTYPEG: DA; QUADMODEL: CON_1U; RATEDVOLTAGE: 50; SIZECODESMD: 2012; VAL1: 1uF(K); VAL2: 100V
C25 = C: ADSMODELNAME: s_GRM1882C1H222JA01D@@; CAPACITANCETOLE: J; CDBNAME: Chip1608_GS_1; COMP: Chip1608_GS_1; COMPONENTTYPE: 4; FNLEADFREETHET1GT2GMCTH1: N_N_N; GCOUNT: 1; MAXGCOUNT: 1; NOMINALCAPACITA: 2.2n; OUMECLASSIFICATION: ƒZƒ‰ƒ~ƒbƒNƒRƒ“ƒfƒ“ƒT; OUMEMAKER: MRT ºc»ì; OUMEMAKERKATAMEI: GRM1882C1H222JA01D@@; PMPRODUCTSTYPEG: DA; QUADMODEL: CON_2.2N; RATEDVOLTAGE: 50; SIZECODESMD: 1608; TEMPCHARACTERI2: CH; VAL1: 2.2nF(J); VAL2: 50V
C26 = C#1: ADSMODELNAME: s__SV_C3225X7R1C226K250AC; CAPACITANCETOLE: K; CDBNAME: Chip3225_GS; CDMASTERCADCELG: KCK0271; COMP: Chip3225_GS; COMPONENTTYPE: 4; CaptureCellPackProp: C##1; FNLEADFREETHET1GT2GMCTH1: N_N_N; GCOUNT: 1; MAXGCOUNT: 1; NOMINALCAPACITA: 22u; OUMECLASSIFICATION: ƒZƒ‰ƒ~ƒbƒNƒRƒ“ƒfƒ“ƒT; OUMEMAKER: TDK ‚s‚c‚j; OUMEMAKERKATAMEI: (SV)C3225X7R1C226K250AC; QUADMODEL: CON_22U; RATEDVOLTAGE: 16; SIZECODESMD: 3225; VAL1: 22uF(K); VAL2: 25V
IC2 = LM46000PWP: CDBNAME: LM46000PWP_GS; COMP: LM46000PWP_GS; COMPONENTTYPE: 4; SAVEAREA0: -78128,-18763,121485,85972; SAVECOUNT: 11; UPDATEDATE: 2019/10/02; UPDATETIME: 09:42:03
L3 = L: CDBNAME: ETQP5M***Y*M_PN; COMP: ETQP5M***Y*M_PN; COMPONENTTYPE: 4; VAL1: 33u(M); VAL2: 3A; VAL3: ETQP5M330YFM
R21 = R: ADSMODELNAME: s_RK73H1JTTD2703D@@; CDBNAME: Chip1608_GS_1; CDMASTERCADCELG: KC0133; COMP: Chip1608_GS_1; COMPONENTTYPE: 4; FNLEADFREETHET1GT2GMCTH1: 3_1_N; GCOUNT: 1; MAXGCOUNT: 1; MOUNTINGFORMSMD: SMD; NOMINALRESISTAN: 270K; OUMECLASSIFICATION: \ÊÀpÅèïRí; OUMEMAKER: KOA R[A; OUMEMAKERKATAMEI: RK73H1JTTD2703D@@; PMPRODUCTSTYPEG: HEV; POWERRATING: 100m; QUADMODEL: RES_270K; RESISTANCETOLER: D; SIZECODESMD: 1608; VAL1: 270k(F); VAL2: 100mW
R22 = R: ADSMODELNAME: s_RK73H1JTD4702F; CDBNAME: Chip1608_GS_1; CDMASTERCADCELG: DR802R; COMP: Chip1608_GS_1; COMPONENTTYPE: 4; FNLEADFREETHET1GT2GMCTH1: 3_1_N; GCOUNT: 1; MAXGCOUNT: 1; MOUNTINGFORMSMD: SMD; NOMINALRESISTAN: 47K; OUMECLASSIFICATION: \ÊÀpÅèïRí; OUMEMAKER: KOA R[A; OUMEMAKERKATAMEI: RK73H1JTD4702F; POWERRATING: 63m; QUADMODEL: RES_47K; RESISTANCETOLER: F; SIZECODESMD: 1608; VAL1: 47k(F); VAL2: 100mW
R23 = R: ADSMODELNAME: s_CR1_16_393FV; CDBNAME: Chip1608_GS_1; CDMASTERCADCELG: DR802R; COMP: Chip1608_GS_1; COMPONENTTYPE: 4; FNLEADFREETHET1GT2GMCTH1: 3_1_N; GCOUNT: 1; MAXGCOUNT: 1; MOUNTINGFORMSMD: SMD; NOMINALRESISTAN: 39K; OUMECLASSIFICATION: \ÊÀpÅèïRí; OUMEMAKER: HDK k¤dCHÆ; OUMEMAKERKATAMEI: CR1/16 393FV; POWERRATING: 63m; QUADMODEL: RES_39K; RESISTANCETOLER: F; SIZECODESMD: 1608; VAL1: 39k(F); VAL2: 100mW
R24 = R: ADSMODELNAME: s_RK73H1JRTTD8201F; CDBNAME: Chip1608_GS_1; CDMASTERCADCELG: KCK0203; COMP: Chip1608_GS_1; COMPONENTTYPE: 4; FNLEADFREETHET1GT2GMCTH1: N_N_N; GCOUNT: 1; MAXGCOUNT: 1; MOUNTINGFORMSMD: SMD; NOMINALRESISTAN: 8.2K; OUMECLASSIFICATION: \ÊÀpÅèïRí; OUMEMAKER: KOA R[A; OUMEMAKERKATAMEI: RK73H1JRTTD8201F; PMPRODUCTSTYPEG: DME; POWERRATING: 100m; QUADMODEL: RES_8.2K; RESISTANCETOLER: F; SIZECODESMD: 1608; VAL1: 8.2k(F); VAL2: 100mW
R25 = R: ADSMODELNAME: s_ERJ3EKF9102V@@; CDBNAME: Chip1608_GS_1; CDMASTERCADCELG: KC0161; COMP: Chip1608_GS_1; COMPONENTTYPE: 4; FNLEADFREETHET1GT2GMCTH1: N_N_N; GCOUNT: 1; MAXGCOUNT: 1; MOUNTINGFORMSMD: SMD; NOMINALRESISTAN: 91K; OUMECLASSIFICATION: \ÊÀpÅèïRí; OUMEMAKER: NAE pi\jbNGNgjbNfoCX; OUMEMAKERKATAMEI: ERJ3EKF9102V@@; PMPRODUCTSTYPEG: DA; POWERRATING: 100m; QUADMODEL: RES_91K; RESISTANCETOLER: F; SIZECODESMD: 1608; VAL1: 91k(F); VAL2: 100mW
U?#3 = WAKU_DEF100: COMPONENTTYPE: 2; DATE: 2022/01/18; DRAWINGNUMBER: RD165-SCHEMATIC-01; FUNCTION: 12 V DC-DC converter; REVISION: 01; SAVEAREA0: 198008,-65938,436964,90161; SAVECOUNT: 4; SHEETNUMBER: 3/3; TITLE: 100W LLC DC-DC Converter; UPDATEDATE: 2022/01/19; UPDATETIME: 11:03:12

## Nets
12V: C7.2 C25.2 C26.1(2) C31.1(2) C33.1(2) IC1.1 IC2.5 IC3.7 IC4.2 L3.2 R25.2 R41.2 R43.2 TP8.1
DN000002: IC3.2 R34.1(2) R38.1
DN000007: C11.1(2) C38.2 T1.4
DN000026: C53.1(2) IC7.7 R53.2
DN000046: IC3.1 R33.1(2)
L_GND: C41.2(1) C45.1 C46.2 D5.1(A) D6.1(A) IC6.2 IC8.3(A2) IC9.5 R67.1 R72.1 R75.2(1)
O_GND: C51.2 C52.2 C53.2(1) C56.2(1) C61.2(1) C62.2(1) C63.2(1) C64.2(1) C65.2(1) C66.2(1) C67.2(1) C68.2(1) C69.2 C71.2 C72.2 C73.2 C74.2 CN5.1 IC7.2 IC7.5 PAD14.1 PAD17.1 Q5.S Q6.S R75.1(2) TP11.1
P-GND: C1.2 C2.2 C3.2 C4.2 C5.2 C7.1 C8.2(1) C11.2(1) C21.1 C22.2 C23.2 C26.2(1) C31.2(1) C32.1 C33.2(1) C34.2 C35.2 C36.2 C39.2 C51.1 CN3.1 D3.1(A) IC1.7 IC2.6 IC2.10 IC2.15 IC2.16 IC2.EP IC3.6 IC4.5 IC5.3 IC6.3 J1.2 PAD7.1 Q2.S Q8.S R22.2 R23.2 R24.1 R33.2(1) R34.2(1) R35.1(2) R39.1 R42.1 R44.1 TP1.1
SIG1: IC7.6 PAD15.1 Q6.D R48.1 T1.10
SIG3: C54.1 IC7.4 PAD12.1 Q5.D T1.6
SIG4: IC5.4 R38.2
SIG5: IC4.4 IC6.4 R41.1 R42.2
SIG6: C22.1 IC2.13 IC2.14 Q3.2(C) R21.1
SIG7: C32.2 IC2.8 IC3.4 Q8.D
SIG67: IC3.8 R31.2
SIG85: C34.1 IC4.3 R43.1 R44.2 R45.2
SIG102: C38.1 C39.1 R37.1
SIG119: CN1.1 L1.1 R1.2
SIG125: D2.3 IC1.8 R8.1
SIG126: IC1.6 R32.1
SIG127: IC1.5 R31.1
SIG128: D1.3 IC1.3 R5.1
SIG129: C6.2 IC1.2
SIG131: C6.1 IC1.4 PAD4.1 PAD5.1 Q1.S Q2.D T1.2
SIG144: C43.1 IC5.2 IC8.2(A0) R63.1 R64.2(1)
SIG154: IC9.3 R71.2 R72.2
SIG160: D5.2(C) Q7.1 R61.2
SIG162: C46.1 D4.2(C) Q7.2 R61.1
SIG166: C52.1 IC7.3
SIG167: IC7.1 R51.2
SIG170: IC7.8 R52.1
SIG172: PAD16.1 Q6.G R52.2
SIG184: IC9.1 R74.2
SIG185: IC6.1 R74.1
SIG190: IC3.5 R32.2
SIG210: PAD13.1 Q5.G R51.1
SIG212: D3.3(AC) R37.2
SIG216: R65.2 R66.1
SIG218: PAD3.1 Q1.G R5.2 R6.2 R7.2(1)
SIG222: D6.2(C) IC9.4 R73.1
SIG225: C42.2 C43.2 IC8.1(A1) R66.2 R67.2
SIG231: PAD6.1 Q2.G R8.2 R9.2 R10.2
SIG233: C36.1 D3.2(C) R35.2(1) R36.1 TP9.1
SIG237: D2.1 R10.1
SIG239: D1.2 R6.1
SIG240: IC4.1 R45.1 R46.2
SIG242: IC5.1 R62.1 R63.2
SIG243: C41.1(2) C45.2 IC9.2 Q7.3 R62.2 R73.2 TP19.1
SIG244: C42.1 R64.1(2)
SIG247: C54.2 R48.2
SIG248: D1.1 R7.1(2)
SIG249: D2.2 R9.1
SIG250: C23.1 IC2.4
SIG251: IC2.7 R23.1
SIG254: C21.2 IC2.11
SIG256: IC2.12 R21.2 R22.1
SIG257: C25.1 IC2.9 R24.2 R25.1
SIG258: C24.2 IC2.1 IC2.2 L3.1
SIG259: C24.1 IC2.3
SIG269: C35.1 IC3.3 R36.2 R39.2
VOUT: C69.1 C71.1 C72.1 C73.1 C74.1 CN4.1 L2.2 R53.1 R71.1
VSEC: C56.1(2) C61.1(2) C62.1(2) C63.1(2) C64.1(2) C65.1(2) C66.1(2) C67.1(2) C68.1(2) D4.1(A) L2.1 R65.1 T1.7 T1.9
N01858: Q8.G R46.1
N04422: C1.1 C2.1 C3.1 C4.1 C5.1 L1.2 PAD2.1 Q1.D Q3.3(E) R1.1 R2.1
N216469: Q3.1(B) R2.2 R3.2
N216829: C8.1(2) R3.1 R4.2
N216837: CN2.1 J1.1 R4.1

Not connected (* = marked no-connect by the designer): T1 1 3 5 8

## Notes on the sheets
sheet 2
- Output & Feed Back
sheet 3
- DC INPUT & Resonance Circuit
